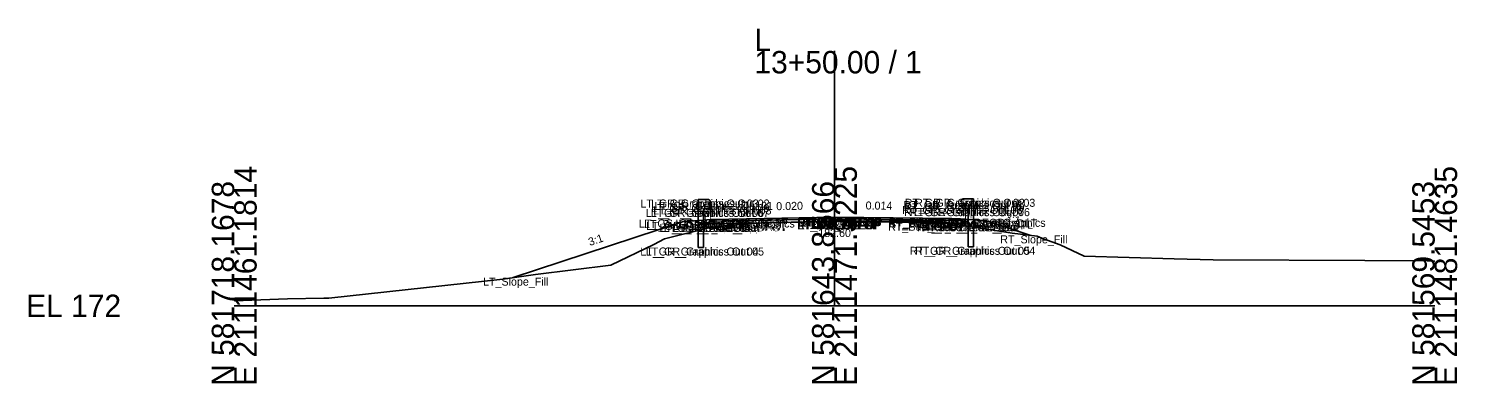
# Model space of a CAD drawing. Extents: x -26 to 3453, y -333 to 9539.
# Drawn here: x -25.7 to 152.8, y 2990.3 to 3034.7 of the extents above; entities that cross this region are included whole.
import ezdxf

# ---------------------------------------------------------------- set-up
doc = ezdxf.new("R2010")
doc.units = 0
for name, color, linetype in [('Default', 7, 'Continuous'), ('Exist Cross Section Cell', 7, 'Continuous'), ('Exist XS Center Line Elevation Label', 7, 'Continuous'), ('Exist XS Ground Line', 7, 'Continuous'), ('Prop CMT Guardrail Graphics', 7, 'Continuous'), ('Prop CMT Pvmt Course 1', 7, 'Continuous'), ('Prop CMT Pvmt Course 2', 7, 'Continuous'), ('Prop CMT Pvmt Course 3', 7, 'Continuous'), ('Prop CMT Pvmt Surface', 7, 'Continuous'), ('Prop CMT Pvmt Surface Shoulder', 7, 'Continuous'), ('Prop CMT Shld Paved Course 1', 7, 'Continuous'), ('Prop CMT Shld Paved Course 2', 7, 'Continuous'), ('Prop CMT Shld Paved Course 3', 7, 'Continuous'), ('Prop CMT Slope Grass', 7, 'Continuous'), ('Prop CMT Subgrade Earthwork', 7, 'Continuous'), ('Prop XS SE Text', 7, 'Continuous'), ('Prop XS Side Slope Text', 7, 'Continuous'), ('Scratch_Level_0', 7, 'Continuous')]:
    doc.layers.add(name, color=color, linetype=linetype)

msp = doc.modelspace()

# ---------------------------------------------------------------- linework, layer by layer
at = {"layer": 'Exist Cross Section Cell'}
for p, q in [((75, 3000), (75, 3031.85)), ((0, 3000), (75, 3000)), ((75, 3000), (150, 3000))]:
    msp.add_line(p, q, dxfattribs=at)
at = {"layer": 'Exist XS Ground Line'}
for p, q in [((60.26, 3009.92), (64.5, 3010.29)), ((64.5, 3010.29), (65.7, 3010.33)), ((65.7, 3010.33), (73.94, 3010.6)), ((73.94, 3010.6), (75, 3010.6)), ((75, 3010.6), (82.58, 3010.6)), ((82.58, 3010.6), (83.87, 3010.59)), ((83.87, 3010.59), (85.05, 3010.62)), ((85.05, 3010.62), (88.48, 3010.48)), ((88.48, 3010.48), (97.19, 3009.09)), ((52.43, 3007.67), (53.78, 3008.38)), ((53.78, 3008.38), (59.31, 3009.74)), ((59.31, 3009.74), (60.26, 3009.92)), ((97.19, 3009.09), (100.34, 3008.72)), ((100.34, 3008.72), (101.11, 3008.38)), ((101.11, 3008.38), (103.19, 3007.63)), ((47.06, 3005.07), (52.43, 3007.67)), ((103.19, 3007.63), (106.21, 3006.23)), ((37.63, 3003.94), (47.06, 3005.07)), ((106.21, 3006.23), (117.45, 3005.88)), ((117.45, 3005.88), (122.33, 3005.75)), ((122.33, 3005.75), (141.29, 3005.65)), ((141.29, 3005.65), (149.08, 3005.63)), ((149.08, 3005.63), (150, 3005.59)), ((11.83, 3000.97), (33.55, 3003.33)), ((33.55, 3003.33), (37.63, 3003.94)), ((0, 3000.64), (6.67, 3000.86)), ((6.67, 3000.86), (11.19, 3000.96)), ((11.19, 3000.96), (11.83, 3000.97))]:
    msp.add_line(p, q, dxfattribs=at)
at = {"layer": 'Prop CMT Guardrail Graphics'}
for points in [[(57.97, 3007.29), (57.97, 3013.29)], [(57.97, 3013.29), (59.3, 3013.29), (59.57, 3013)], [(59.57, 3012.42), (59.3, 3012.12), (58.64, 3012.12)], [(58.64, 3012.12), (58.64, 3007.29)], [(59.57, 3013), (59.3, 3012.71)], [(59.3, 3012.71), (59.57, 3012.42)], [(92.36, 3013.38), (91.03, 3013.38), (90.75, 3013.09)], [(90.75, 3013.09), (91.03, 3012.8)], [(91.03, 3012.8), (90.75, 3012.5)], [(90.75, 3012.5), (91.03, 3012.21), (91.69, 3012.21)], [(91.69, 3012.21), (91.69, 3007.38)], [(92.36, 3007.38), (92.36, 3013.38)], [(58.64, 3007.29), (57.97, 3007.29)], [(91.69, 3007.38), (92.36, 3007.38)]]:
    msp.add_lwpolyline(points, dxfattribs=at)
at = {"layer": 'Prop CMT Pvmt Course 1'}
for points in [[(75, 3011.1), (64, 3010.88)], [(64, 3010.67), (75, 3010.89)], [(64, 3010.88), (64, 3010.67)], [(75, 3010.89), (75, 3011.1)], [(75, 3011.1), (86, 3010.95)], [(75, 3010.89), (75, 3011.1)], [(86, 3010.74), (75, 3010.89)], [(86, 3010.95), (86, 3010.74)]]:
    msp.add_lwpolyline(points, dxfattribs=at)
msp.add_lwpolyline([(75, 3010.89), (75, 3010.97), (75, 3010.97), (75, 3010.89)], close=True, dxfattribs=at)
msp.add_lwpolyline([(75, 3010.89), (75, 3010.97), (75, 3010.97), (75, 3010.89)], close=True, dxfattribs=at)
at = {"layer": 'Prop CMT Pvmt Course 2'}
for points in [[(75, 3010.89), (64, 3010.67)], [(64, 3010.67), (64, 3010.34)], [(64, 3010.34), (75, 3010.56)], [(75, 3010.56), (75, 3010.89)], [(75, 3010.56), (75, 3010.89)], [(75, 3010.89), (86, 3010.74)], [(86, 3010.4), (75, 3010.56)], [(86, 3010.74), (86, 3010.4)]]:
    msp.add_lwpolyline(points, dxfattribs=at)
at = {"layer": 'Prop CMT Pvmt Course 3'}
for points in [[(75, 3010.56), (64, 3010.34)], [(64, 3010.34), (75, 3010.56)], [(64, 3010.34), (64, 3010.34)], [(75, 3010.56), (75, 3010.56)], [(75, 3010.56), (86, 3010.4)], [(86, 3010.4), (75, 3010.56)], [(75, 3010.56), (75, 3010.56)], [(86, 3010.4), (86, 3010.4)]]:
    msp.add_lwpolyline(points, dxfattribs=at)
at = {"layer": 'Prop CMT Pvmt Surface'}
for points in [[(75, 3011.1), (64, 3010.88)], [(75, 3011.1), (86, 3010.95)]]:
    msp.add_lwpolyline(points, dxfattribs=at)
at = {"layer": 'Prop CMT Pvmt Surface Shoulder'}
for points in [[(64, 3010.88), (59.58, 3010.79)], [(86, 3010.95), (90.74, 3010.88)]]:
    msp.add_lwpolyline(points, dxfattribs=at)
at = {"layer": 'Prop CMT Shld Paved Course 1'}
for points in [[(64, 3010.88), (59.58, 3010.79), (59.37, 3010.58)], [(59.37, 3010.58), (64, 3010.67)], [(64, 3010.67), (64, 3010.88)], [(86, 3010.95), (90.74, 3010.88), (90.96, 3010.67)], [(86, 3010.74), (86, 3010.95)], [(90.96, 3010.67), (86, 3010.74)]]:
    msp.add_lwpolyline(points, dxfattribs=at)
at = {"layer": 'Prop CMT Shld Paved Course 2'}
for points in [[(64, 3010.67), (59.37, 3010.58), (59.03, 3010.24)], [(59.03, 3010.24), (64, 3010.34)], [(64, 3010.34), (64, 3010.67)], [(86, 3010.74), (90.96, 3010.67), (91.29, 3010.33)], [(86, 3010.4), (86, 3010.74)], [(91.29, 3010.33), (86, 3010.4)]]:
    msp.add_lwpolyline(points, dxfattribs=at)
at = {"layer": 'Prop CMT Shld Paved Course 3'}
for points in [[(64, 3010.34), (59.03, 3010.24)], [(59.03, 3010.24), (64, 3010.34)], [(59.03, 3010.24), (59.03, 3010.24), (59.03, 3010.24)], [(64, 3010.34), (64, 3010.34)], [(86, 3010.4), (91.29, 3010.33)], [(91.29, 3010.33), (86, 3010.4)], [(86, 3010.4), (86, 3010.4)], [(91.29, 3010.33), (91.29, 3010.33), (91.29, 3010.33)]]:
    msp.add_lwpolyline(points, dxfattribs=at)
at = {"layer": 'Prop CMT Slope Grass'}
for points in [[(56, 3010.5), (34.86, 3003.53)], [(59.57, 3010.79), (56, 3010.5)], [(59.58, 3010.79), (59.57, 3010.79)], [(90.74, 3010.88), (90.75, 3010.88)], [(90.75, 3010.88), (94, 3010.64)], [(94, 3010.64), (99.54, 3008.81)]]:
    msp.add_lwpolyline(points, dxfattribs=at)
at = {"layer": 'Prop CMT Subgrade Earthwork'}
for points in [[(59.03, 3010.24), (58.56, 3010.71)], [(64, 3010.34), (59.03, 3010.24)], [(75, 3010.56), (64, 3010.34)], [(75, 3010.56), (86, 3010.4)], [(86, 3010.4), (91.29, 3010.33)], [(91.29, 3010.33), (91.77, 3010.8)]]:
    msp.add_lwpolyline(points, dxfattribs=at)

# ---------------------------------------------------------------- texts
at = {"layer": 'Default'}
msp.add_text('-', height=0.0001, dxfattribs=at).set_placement((0, 3000))
at = {"layer": 'Exist Cross Section Cell'}
for s, p in [('L', (65, 3031.85)), ('13+50.00 / 1', (65, 3029.05)), ('EL 172', (-26, 2998.6))]:
    msp.add_text(s, height=2.8, dxfattribs=at).set_placement(p)
for s, p in [('E 2111461.1814', (2.8, 2990)), ('E 2111471.3225', (77.8, 2990)), ('E 2111481.4635', (152.8, 2990)), ('N 581718.1678', (0, 2990)), ('N 581643.8566', (75, 2990)), ('N 581569.5453', (150, 2990))]:
    msp.add_text(s, height=2.8, rotation=90, dxfattribs=at).set_placement(p)
at = {"layer": 'Exist XS Center Line Elevation Label'}
msp.add_text('182.60', height=1, dxfattribs=at).set_placement((72.97, 3008.6))
at = {"layer": 'Prop XS SE Text'}
for s, rotation, p in [('0.020', 1.1458, (67.73, 3011.95)), ('0.014', 359.1979, (78.89, 3012.05))]:
    msp.add_text(s, height=1, rotation=rotation, dxfattribs=at).set_placement(p)
at = {"layer": 'Prop XS Side Slope Text'}
for rotation, p in [(341.7371, (96.25, 3010.69)), (18.2629, (44.44, 3007.48))]:
    msp.add_text('3:1', height=1, rotation=rotation, dxfattribs=at).set_placement(p)
at = {"layer": 'Scratch_Level_0'}
for s, p in [('LT_GR_Graphics Out 03', (50.75, 3012.29)), ('LT_GR_Graphics Out 06', (51.41, 3011.12)), ('LT_GR_Graphics Out 07', (52.06, 3011.12)), ('LT_GR_Graphics Out 09', (52.08, 3011.71)), ('LT_GR_Graphics Out 02', (52.1, 3012.29)), ('LT_GR_Graphics Out 08', (52.34, 3011.42)), ('LT_GR_Graphics Out 01', (52.52, 3012)), ('RT_GR_Graphics Out 08', (83.47, 3011.5)), ('RT_GR_Graphics Out 01', (83.64, 3012.09)), ('RT_GR_Graphics Out 07', (83.72, 3011.21)), ('RT_GR_Graphics Out 09', (83.74, 3011.8)), ('RT_GR_Graphics Out 02', (83.77, 3012.38)), ('RT_GR_Graphics Out 06', (84.41, 3011.21)), ('RT_GR_Graphics Out 03', (85.08, 3012.38)), ('LT_GS_OS_GR_Face_Graphics', (50.57, 3009.79)), ('LT_Sub_Trench_Out_DLT', (51.21, 3009.71)), ('LT_GS_OS_CTL', (51.46, 3009.5)), ('LT_Sub_Trench_Out', (53.14, 3009.24)), ('LT_PS3_Shelf_Out', (53.69, 3009.24)), ('LT_PS3_OEOP', (54.82, 3009.24)), ('LT_PS2_OEOP', (55.16, 3009.58)), ('LT_PS1_OEOP', (55.49, 3009.79)), ('LT_PV2_OEOT', (59.75, 3009.67)), ('LT_PV3_OEOT', (59.75, 3009.34)), ('LT_Sub_OEOT', (59.77, 3009.34)), ('LT_PV1_OEOT', (59.87, 3009.88)), ('RT_PV2_OEEOP', (70.33, 3009.89)), ('RT_PV3_OEEOP', (70.33, 3009.56)), ('RT_Sub_OEEOP', (70.36, 3009.56)), ('LT_PV2_OEEOP', (70.39, 3009.89)), ('LT_PV3_OEEOP', (70.39, 3009.56)), ('LT_Sub_OEEOP', (70.42, 3009.56)), ('RT_PV1_OEEOP', (70.45, 3009.97)), ('LT_PV1_OEEOP', (70.51, 3009.97)), ('RT_PV2_IEEOP', (70.71, 3009.89)), ('LT_PV2_IEEOP', (70.77, 3009.89)), ('RT_PV1_IEEOP', (70.83, 3009.97)), ('LT_PV1_IEEOP', (70.89, 3009.97)), ('PV2_PGL', (72.35, 3009.89)), ('PV1_PGL', (72.47, 3010.1)), ('RT_GS_OS_GR_Face_Graphics', (81.69, 3009.88)), ('RT_PV2_OEOT', (81.69, 3009.74)), ('RT_PV3_OEOT', (81.69, 3009.4)), ('RT_Sub_OEOT', (81.71, 3009.4)), ('RT_PV1_OEOT', (81.81, 3009.95)), ('RT_Sub_Trench_Out_DLT', (84.36, 3009.8)), ('RT_Sub_Trench_Out', (85.34, 3009.33)), ('RT_PS3_Shelf_Out', (85.89, 3009.33)), ('RT_PS1_OEOP', (86.59, 3009.88)), ('RT_PS2_OEOP', (86.68, 3009.67)), ('RT_PS3_OEOP', (87.02, 3009.33)), ('RT_GS_OS_CTL', (89.4, 3009.64)), ('RT_Slope_Fill', (95.72, 3007.81)), ('LT_GR_Graphics Out 04', (50.74, 3006.29)), ('LT_GR_Graphics Out 05', (51.41, 3006.29)), ('RT_GR_Graphics Out 05', (84.41, 3006.38)), ('RT_GR_Graphics Out 04', (85.07, 3006.38)), ('LT_Slope_Fill', (31.09, 3002.53))]:
    msp.add_text(s, height=1, dxfattribs=at).set_placement(p)

doc.saveas('drawing.dxf')
